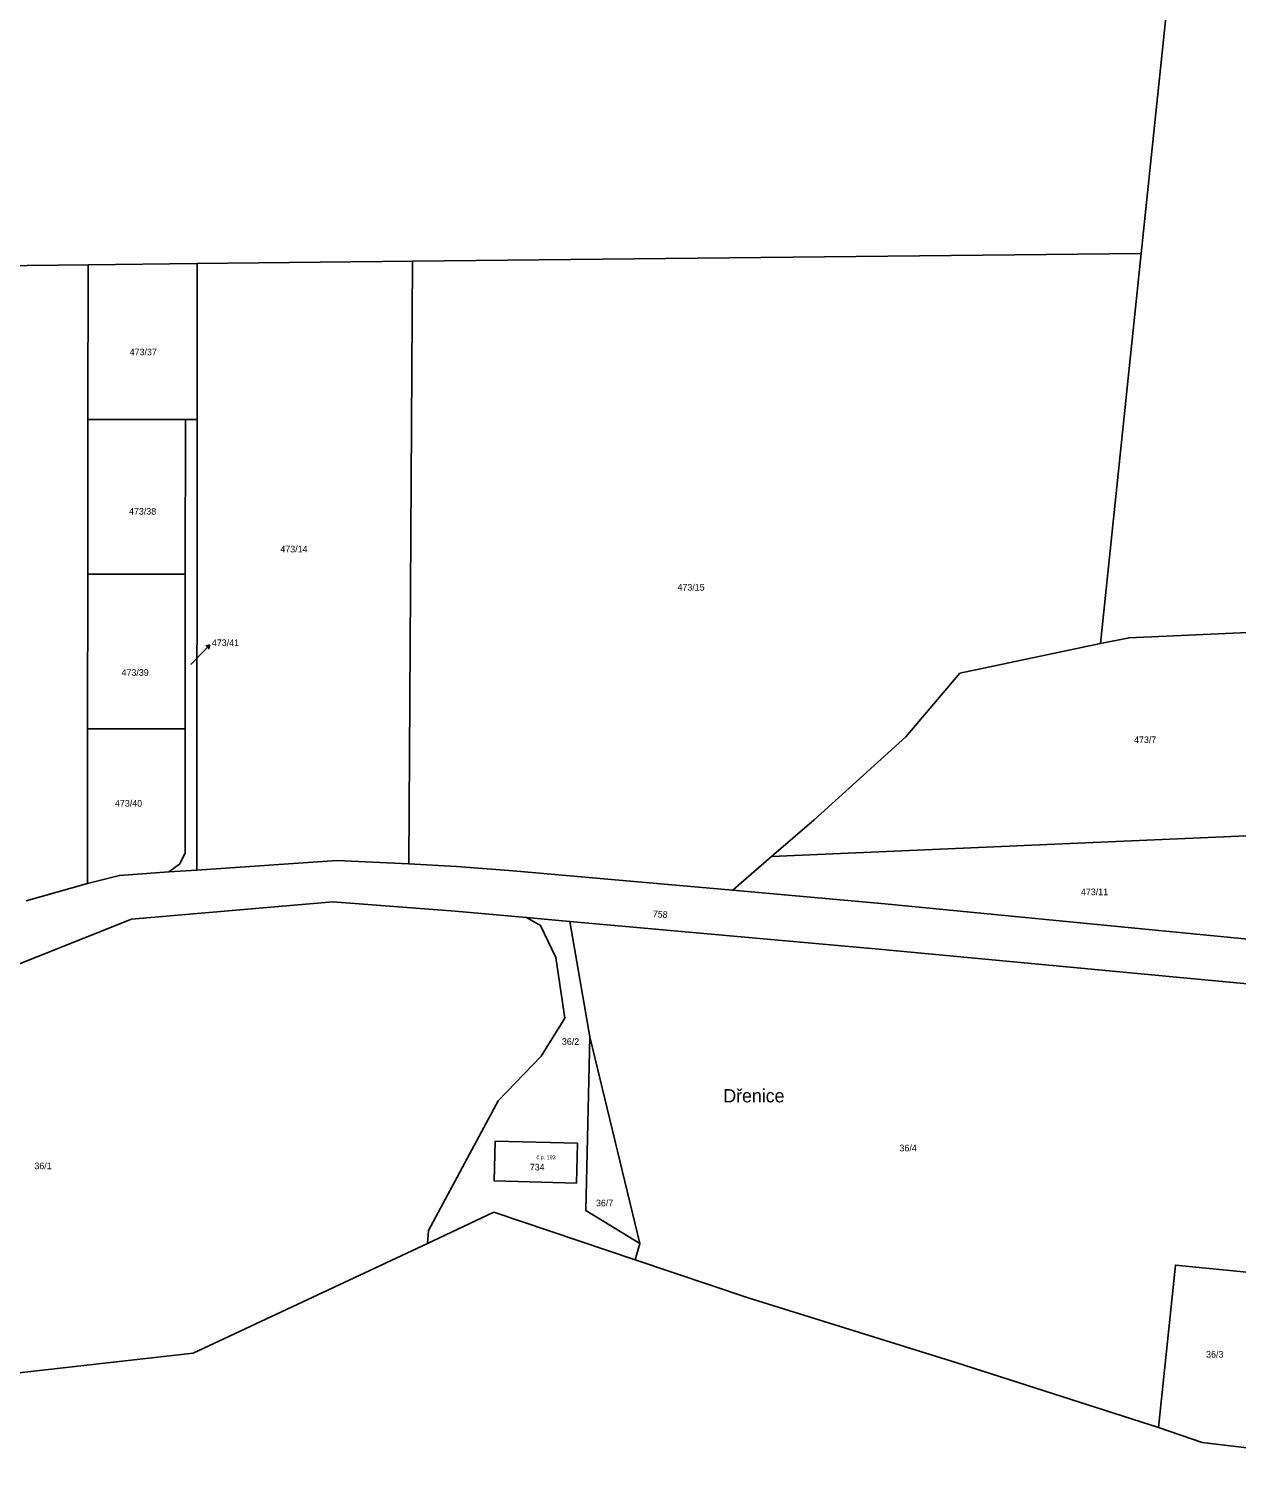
# Model space of a CAD drawing. Extents: x -887272 to -877616, y -1026687 to -1019819.
# Drawn here: x -883368.4 to -883058.7, y -1024089.6 to -1023717 of the extents above; entities that cross this region are included whole.
import ezdxf

# ---------------------------------------------------------------- set-up
doc = ezdxf.new("R2010")
doc.units = 0
for name, color, linetype in [('Definiční body', 7, 'Continuous'), ('Hranice parcel', 7, 'Continuous'), ('Parcelní čísla', 7, 'Continuous'), ('Polygon budovy', 7, 'Continuous'), ('Pop  PČ popisy', 7, 'Continuous')]:
    doc.layers.add(name, color=color, linetype=linetype)

msp = doc.modelspace()

# ---------------------------------------------------------------- linework, layer by layer
at = {"layer": 'Hranice parcel'}
for p, q in [((-883325.3, -1023777.1), (-883270.1, -1023776.5)), ((-883271.05, -1023930.97), (-883270.1, -1023776.5)), ((-883270.1, -1023776.5), (-883083.3, -1023774.48)), ((-883083.3, -1023774.48), (-883093.7, -1023874.44)), ((-883390.32, -1023777.79), (-883353.3, -1023777.4)), ((-883353.33, -1023817.05), (-883353.3, -1023777.4)), ((-883353.3, -1023777.4), (-883325.3, -1023777.1)), ((-883325.3, -1023777.1), (-883325.34, -1023817.07)), ((-883353.37, -1023856.7), (-883353.33, -1023817.05)), ((-883353.33, -1023817.05), (-883328.34, -1023817.07)), ((-883328.37, -1023856.72), (-883328.34, -1023817.07)), ((-883328.34, -1023817.07), (-883325.34, -1023817.07)), ((-883325.34, -1023817.07), (-883325.44, -1023932.53)), ((-883353.4, -1023896.35), (-883353.37, -1023856.7)), ((-883353.37, -1023856.7), (-883328.37, -1023856.72)), ((-883328.41, -1023896.37), (-883328.37, -1023856.72)), ((-883353.44, -1023936), (-883353.4, -1023896.35)), ((-883353.4, -1023896.35), (-883328.41, -1023896.37)), ((-883178.1, -1023929.02), (-883026.61, -1023922.44)), ((-883178.1, -1023929.02), (-883187.84, -1023937.5)), ((-883332.57, -1023933.02), (-883329.87, -1023931.04)), ((-883325.44, -1023932.53), (-883332.57, -1023933.02)), ((-883353.44, -1023936), (-883369.18, -1023940.44)), ((-883187.84, -1023937.5), (-883188.08, -1023937.71)), ((-883229.75, -1023945.68), (-883240.89, -1023944.68)), ((-883224.67, -1023975.29), (-883229.75, -1023945.68)), ((-883224.67, -1023975.29), (-883211.85, -1024028.22)), ((-883213.06, -1024032.41), (-883211.85, -1024028.22))]:
    msp.add_line(p, q, dxfattribs=at)
for points in [[(-883061.09, -1023541.51), (-883058.83, -1023540.64), (-883083.3, -1023774.48)], [(-883093.7, -1023874.44), (-883086.38, -1023873.01), (-883023.64, -1023870.22)], [(-883093.7, -1023874.44), (-883129.75, -1023882.03), (-883143.66, -1023898.37), (-883167.16, -1023919.64), (-883178.1, -1023929.02)], [(-883329.87, -1023931.04), (-883328.43, -1023928.23), (-883328.41, -1023896.37)], [(-883332.57, -1023933.02), (-883345.24, -1023933.9), (-883353.44, -1023936)], [(-883271.05, -1023930.97), (-883289.54, -1023930.04), (-883325.44, -1023932.53)], [(-883188.08, -1023937.71), (-883244.27, -1023932.76), (-883258.84, -1023931.58), (-883271.05, -1023930.97)], [(-883240.89, -1023944.68), (-883259.18, -1023943.04), (-883290.58, -1023940.7), (-883342.16, -1023945.12), (-883390.28, -1023964.24)], [(-883188.08, -1023937.71), (-883148.98, -1023941.16), (-883038.36, -1023951.95)], [(-883266.28, -1024028.21), (-883265.99, -1024024.94), (-883248.11, -1023991.69), (-883237.16, -1023980.19), (-883231.07, -1023970.46), (-883233.36, -1023954.91), (-883237.28, -1023946.74), (-883240.89, -1023944.68)], [(-883024.78, -1023962.34), (-883038.88, -1023963.34), (-883149.62, -1023952.88), (-883229.75, -1023945.68)], [(-883211.85, -1024028.22), (-883225.63, -1024019.74), (-883224.67, -1023975.29)], [(-883227.8, -1024002.55), (-883228.06, -1024012.74), (-883249.17, -1024012.19), (-883248.91, -1024002.02), (-883227.8, -1024002.55)], [(-883213.06, -1024032.41), (-883249.22, -1024020.2), (-883266.28, -1024028.21)], [(-883469.7, -1024089.6), (-883449.24, -1024083.76), (-883375.54, -1024061.88), (-883326.34, -1024056.38), (-883266.28, -1024028.21)], [(-883213.06, -1024032.41), (-883184.04, -1024042.2), (-883130.8, -1024058.74), (-883078.86, -1024075.42)], [(-883054.46, -1024035.79), (-883074.51, -1024033.76), (-883078.86, -1024075.42)], [(-883078.86, -1024075.42), (-883067.68, -1024079.26), (-883047.64, -1024081.6)]]:
    msp.add_lwpolyline(points, dxfattribs=at)
at = {"layer": 'Polygon budovy'}
msp.add_lwpolyline([(-883227.8, -1024002.55), (-883248.91, -1024002.02), (-883249.17, -1024012.19), (-883228.06, -1024012.74)], close=True, dxfattribs=at)
at = {"layer": 'Pop  PČ popisy'}
for p, q in [((-883326.96, -1023879.85), (-883324.16, -1023876.97)), ((-883324.16, -1023876.97), (-883322.08, -1023874.81)), ((-883322.08, -1023874.81), (-883323.13, -1023875.18)), ((-883322.08, -1023874.81), (-883322.41, -1023875.88))]:
    msp.add_line(p, q, dxfattribs=at)

# ---------------------------------------------------------------- texts
at = {"layer": 'Definiční body'}
msp.add_text('č.p. 193', height=1, dxfattribs=at).set_placement((-883238.33, -1024006.65))
at = {"layer": 'Parcelní čísla'}
for s, p in [('473/37', (-883342.62, -1023800.6)), ('473/38', (-883342.79, -1023841.44)), ('473/14', (-883303.99, -1023851.12)), ('473/15', (-883202.16, -1023860.91)), ('473/41', (-883321.55, -1023875.13)), ('473/39', (-883344.7, -1023882.75)), ('473/7', (-883085.1, -1023899.99)), ('473/40', (-883346.4, -1023916.28)), ('473/11', (-883098.71, -1023938.97)), ('36/2', (-883231.8, -1023977.33)), ('36/4', (-883145.24, -1024004.62)), ('36/1', (-883367.06, -1024009.2)), ('734', (-883240.03, -1024009.52)), ('36/7', (-883223.06, -1024018.71)), ('36/3', (-883066.63, -1024057.5))]:
    msp.add_text(s, height=1.7, dxfattribs=at).set_placement(p)
msp.add_text('758', height=1.7, rotation=356, dxfattribs=at).set_placement((-883208.54, -1023944.57))
at = {"layer": 'Pop  PČ popisy'}
msp.add_text('Dřenice', height=3.4, dxfattribs=at).set_placement((-883190.41, -1023992.07))

doc.saveas('drawing.dxf')
